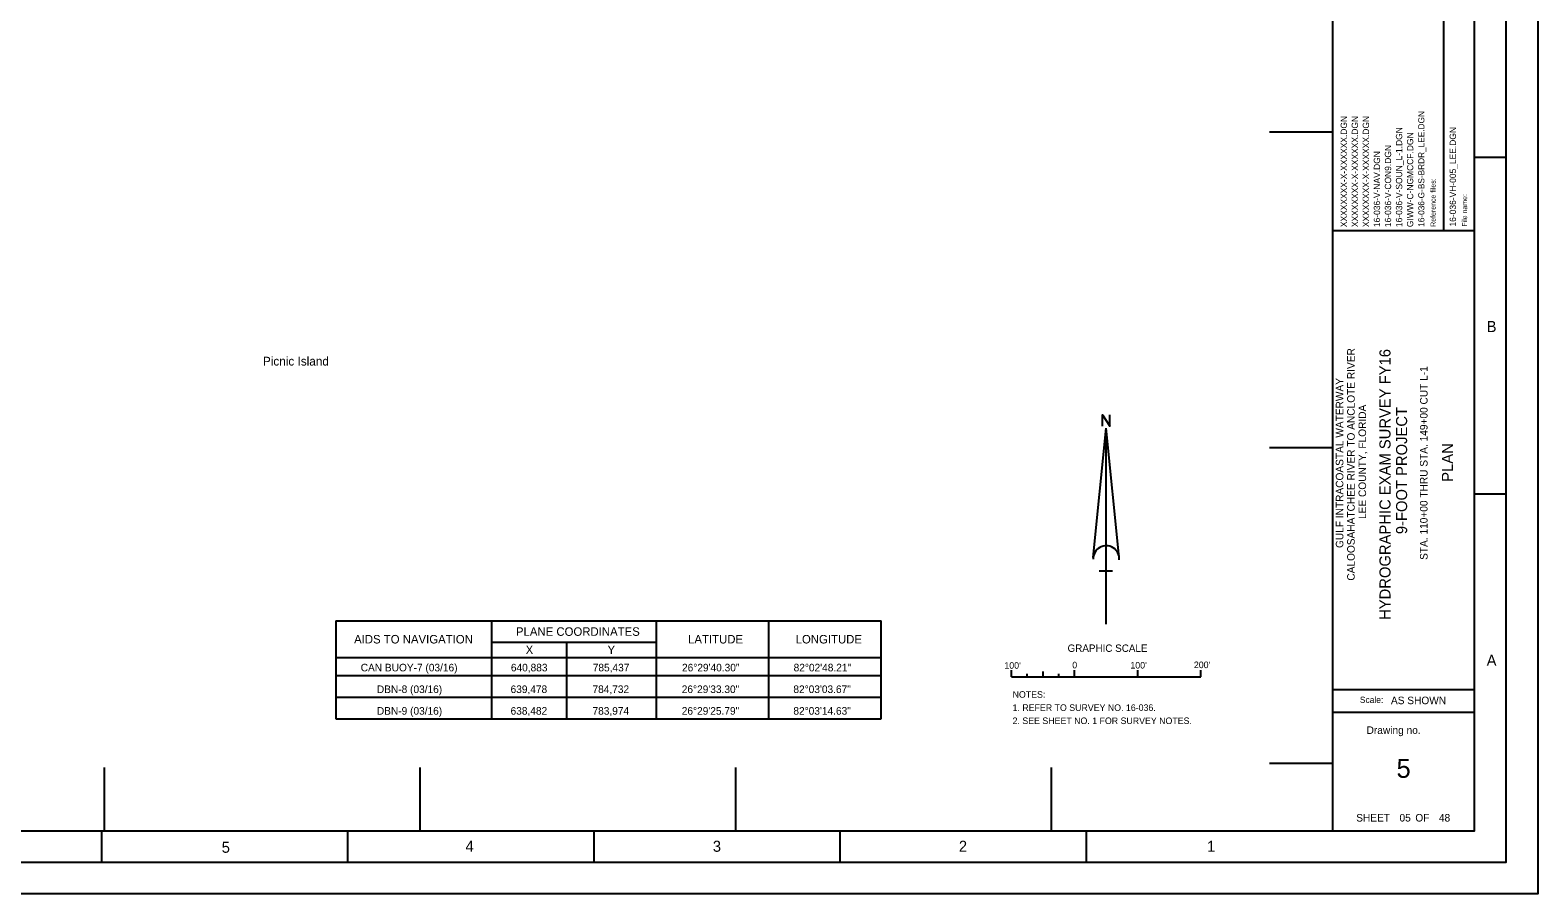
# Model space of a CAD drawing. Extents: x 637370 to 641771, y 782793 to 786193.
# Drawn here: x 639382 to 641771, y 782793 to 784161 of the extents above; entities that cross this region are included whole.
import ezdxf

# ---------------------------------------------------------------- set-up
doc = ezdxf.new("R2010")
doc.units = 0
for name, color, linetype in [('G-ANNO-NPLT', 7, 'Continuous'), ('G-ANNO-TEXT-DRWG', 7, 'Continuous'), ('G-ANNO-TEXT-PROJ', 7, 'Continuous'), ('G-ANNO-TEXT-TTLB', 7, 'Continuous'), ('G-ANNO-TTLB', 7, 'Continuous'), ('V-ANNO-NOTE', 7, 'Continuous'), ('V-ANNO-SCHD', 7, 'Continuous'), ('V-ANNO-SYMB', 7, 'Continuous'), ('V-SITE-IDEN', 7, 'Continuous'), ('V-TOPO-COOR-STAT', 7, 'Continuous')]:
    doc.layers.add(name, color=color, linetype=linetype)

msp = doc.modelspace()

# ---------------------------------------------------------------- linework, layer by layer
at = {"layer": 'G-ANNO-NPLT'}
msp.add_lwpolyline([(637370.5, 786192.8), (641770.5, 786192.8), (641770.5, 782792.8), (637370.5, 782792.8)], close=True, dxfattribs=at)
msp.add_lwpolyline([(641770.6, 782842.8), (641770.6, 782792.8), (641720.6, 782792.8)], dxfattribs=at)
at = {"layer": 'G-ANNO-TTLB'}
for p, q in [((641445.4, 786092.8), (641445.4, 782892.8)), ((641621.2, 784194.9), (641621.2, 783843.5)), ((641720.5, 783959.4), (641670.5, 783959.4)), ((641445.5, 783843.5), (641670.5, 783843.5)), ((641720.5, 783426.1), (641670.5, 783426.1)), ((641445.4, 783116.5), (641670.5, 783116.5)), ((641445.4, 783080.8), (641670.5, 783080.8)), ((639495.5, 782842.8), (639495.5, 782892.8)), ((639885.5, 782842.8), (639885.5, 782892.8)), ((640275.5, 782842.8), (640275.5, 782892.8)), ((640665.5, 782842.8), (640665.5, 782892.8)), ((641055.5, 782842.8), (641055.5, 782892.8))]:
    msp.add_line(p, q, dxfattribs=at)
for points in [[(637420.5, 782842.8), (641720.5, 782842.8), (641720.5, 786142.8), (637420.5, 786142.8)], [(641670.5, 786092.8), (637545.5, 786092.8), (637545.5, 782892.8), (641670.5, 782892.8)]]:
    msp.add_lwpolyline(points, close=True, dxfattribs=at)
at = {"layer": 'V-ANNO-NOTE'}
for p, q in [((640936.8, 783136.6), (640936.8, 783147.1)), ((640936.8, 783136.6), (641236.8, 783136.6)), ((640961.8, 783136.6), (640961.8, 783141.4)), ((640986.8, 783136.6), (640986.8, 783145.1)), ((641011.8, 783136.6), (641011.8, 783141.4)), ((641036.8, 783136.6), (641036.8, 783147.1)), ((641036.8, 783136.6), (641036.8, 783147.1)), ((641036.8, 783136.6), (641036.8, 783141.6)), ((641136.8, 783136.6), (641136.8, 783147.1)), ((641236.8, 783136.6), (641236.8, 783147.1))]:
    msp.add_line(p, q, dxfattribs=at)
at = {"layer": 'V-ANNO-SCHD'}
for p, q in [((639866.3, 783225.1), (640730.4, 783225.1)), ((639866.3, 783225.1), (639866.3, 783069.9)), ((640113, 783225.1), (640113, 783069.9)), ((640373.7, 783225.1), (640373.7, 783069.9)), ((640552, 783225.1), (640552, 783069.9)), ((640730.4, 783069.9), (640730.4, 783225.1)), ((640113, 783191.4), (640373.7, 783191.4)), ((640231.9, 783191.4), (640231.9, 783069.9)), ((639866.3, 783167.3), (640730.4, 783167.3)), ((639866.3, 783138.4), (640730.4, 783138.4)), ((639866.3, 783104.2), (640729.9, 783104.2)), ((639866.3, 783069.9), (640730.4, 783069.9))]:
    msp.add_line(p, q, dxfattribs=at)
at = {"layer": 'V-ANNO-SYMB'}
for p, q in [((641066.2, 783325.6), (641086.8, 783530.4)), ((641086.8, 783220.1), (641086.8, 783530.4)), ((641107.4, 783325.6), (641086.8, 783530.4)), ((641096.6, 783303.9), (641075.9, 783303.9))]:
    msp.add_line(p, q, dxfattribs=at)
msp.add_lwpolyline([(641081.1, 783533.7), (641081.1, 783551.8), (641092.3, 783533.7), (641092.3, 783551.8)], dxfattribs=at)
msp.add_arc((641086.8, 783323.5), 20.7, 355.2984, 182.0673, dxfattribs=at)
at = {"layer": 'V-TOPO-COOR-STAT'}
for p, q in [((641345.4, 784000), (641445.4, 784000)), ((641345.4, 783500), (641445.4, 783500)), ((639500, 782892.8), (639500, 782992.8)), ((640000, 782892.8), (640000, 782992.8)), ((640500, 782892.8), (640500, 782992.8)), ((641000, 782892.8), (641000, 782992.8)), ((641345.4, 783000), (641445.4, 783000))]:
    msp.add_line(p, q, dxfattribs=at)

# ---------------------------------------------------------------- texts
at = {"layer": 'G-ANNO-TEXT-DRWG'}
for s, height, p in [('XXXXXXXX-X-XXXXXX.DGN', 10, (641468.2, 783848.9)), ('XXXXXXXX-X-XXXXXX.DGN', 10, (641485.7, 783848.9)), ('XXXXXXXX-X-XXXXXX.DGN', 10, (641503.2, 783848.9)), ('16-036-V-SOUN_L-1.DGN', 10, (641555.7, 783848.9)), ('GIWW-C-NGMCCF.DGN', 10, (641573.2, 783848.9)), ('16-036-VH-005_LEE.DGN', 10, (641640.9, 783849.9)), ('16-036-V-CON9.DGN', 10, (641538.2, 783848.9)), ('16-036-V-NAV.DGN', 10, (641520.7, 783848.9)), ('STA. 110+00 THRU STA. 149+00 CUT L-1', 12, (641595.9, 783321.8)), ('PLAN', 17.5, (641636.1, 783445.5))]:
    msp.add_text(s, height=height, rotation=90, dxfattribs=at).set_placement(p)
for s, height, p in [('5', 30, (641546.8, 782976.6)), (' 05          48', 12, (641547, 782907.3))]:
    msp.add_text(s, height=height, dxfattribs=at).set_placement(p)
at = {"layer": 'G-ANNO-TEXT-PROJ'}
for s, height, p in [('16-036-G-BS-BRDR_LEE.DGN', 9.8, (641590.9, 783849.3)), ('CALOOSAHATCHEE RIVER TO ANCLOTE RIVER', 12, (641480.5, 783288.9)), ('HYDROGRAPHIC EXAM SURVEY FY16', 17.5, (641537.2, 783226.7)), ('GULF INTRACOASTAL WATERWAY', 12, (641462.5, 783340.6)), ('LEE COUNTY, FLORIDA', 12, (641498.5, 783386.6)), ('9-FOOT PROJECT', 17.5, (641563.5, 783362.5))]:
    msp.add_text(s, height=height, rotation=90, dxfattribs=at).set_placement(p)
at = {"layer": 'G-ANNO-TEXT-TTLB'}
for s, p in [('Reference files:', (641608.6, 783849.4)), ('File name:', (641658.6, 783849.6))]:
    msp.add_text(s, height=8, rotation=90, dxfattribs=at).set_placement(p)
for s, height, p in [('Scale:', 10, (641488.6, 783095.2)), ('AS SHOWN', 12, (641537.9, 783093.2)), ('Drawing no.', 12, (641499.3, 783046.1)), ('SHEET         OF', 12, (641482.9, 782907.3))]:
    msp.add_text(s, height=height, dxfattribs=at).set_placement(p)
at = {"layer": 'G-ANNO-TTLB'}
for s, p in [('B', (641689.5, 783682.7)), ('A', (641689.5, 783154)), ('5', (639685.6, 782857.8)), ('4', (640071.8, 782859.4)), ('3', (640463.6, 782859.4)), ('2', (640853.4, 782859.4)), ('1', (641246.6, 782859.4))]:
    msp.add_text(s, height=17.5, dxfattribs=at).set_placement(p)
at = {"layer": 'V-ANNO-NOTE'}
for s, height, p in [('GRAPHIC SCALE', 11.666, (641025.6, 783176.1)), ("100'", 10.42, (640925.5, 783149.3)), ('0', 10.4, (641033.1, 783150)), ("100'", 10.42, (641125.1, 783149.7)), ("200'", 10.42, (641225.7, 783150.3)), ('NOTES:', 10.42, (640938.5, 783103.4)), ('1. REFER TO SURVEY NO. 16-036.', 10.416, (640938.5, 783082.5)), ('2. SEE SHEET NO. 1 FOR SURVEY NOTES.', 10.416, (640938.5, 783061.7))]:
    msp.add_text(s, height=height, dxfattribs=at).set_placement(p)
at = {"layer": 'V-ANNO-SCHD'}
for s, height, p in [('PLANE COORDINATES', 13.471, (640151.7, 783201.5)), ('AIDS TO NAVIGATION', 13.471, (639895.3, 783189.4)), ('X', 13.5, (640167.1, 783172.6)), ('Y', 13.5, (640296.8, 783172.6)), ('LATITUDE', 13.47, (640424.4, 783189.4)), ('LONGITUDE', 13.47, (640594.8, 783189.4))]:
    msp.add_text(s, height=height, rotation=0.0001, dxfattribs=at).set_placement(p)
at = {"layer": 'V-ANNO-SYMB'}
for s, p in [('CAN BUOY-7 (03/16)', (639905.8, 783145.2)), ('640,883', (640143.7, 783145.2)), ('785,437', (640273.4, 783145.2)), ('26%%D29\'40.30"', (640414.8, 783145.2)), ('82%%D02\'48.21"', (640591.6, 783145.2)), ('DBN-8 (03/16)', (639931.4, 783110.9)), ('639,478', (640143.2, 783110.9)), ('784,732', (640273, 783110.9)), ('26%%D29\'33.30"', (640414.4, 783110.9)), ('82%%D03\'03.67"', (640591.2, 783110.9)), ('DBN-9 (03/16)', (639931.4, 783076.6)), ('638,482', (640143.2, 783076.6)), ('783,974', (640273, 783076.6)), ('26%%D29\'25.79"', (640414.4, 783076.6)), ('82%%D03\'14.63"', (640591.2, 783076.6))]:
    msp.add_text(s, height=12, dxfattribs=at).set_placement(p)
at = {"layer": 'V-SITE-IDEN'}
msp.add_text('Picnic Island', height=13.92, dxfattribs=at).set_placement((639750.9, 783629.6))

doc.saveas('drawing.dxf')
